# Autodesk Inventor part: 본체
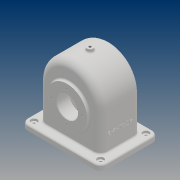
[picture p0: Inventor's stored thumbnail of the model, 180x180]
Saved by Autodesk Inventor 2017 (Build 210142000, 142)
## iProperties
Part Number: 본체
Material: 일반
Document SubType Name: Modeling
Designer: 20
Density: 1 g/cm^3
Appearance: 기본값
Author: 20
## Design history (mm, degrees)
sketch "스케치2"
  geometry: L1 (58, 0)-(58, -78); L2 (-58, 0)-(-58, -78); L3 (58, -78)-(-58, -78); A1 r 58 centre (0, 0) between (58, 0) and (-58, 0); 1 further point
  constraints: 6 end point, 2 point on circle, 2 tangent, 2 vertical, 1 centre point, 1 coincident, 1 horizontal
  dimensions: "d1" = 116 diameter of A1; "d2" = 78 distance of L2.start L2.end
extrude "돌출1" new body sketch "스케치2" stored distance "d3" = 77; taper "d4" = 0 deg
sketch "스케치9"
  geometry: L1 (-58, -78)-(58, -78) reference; C1 r 38 at (0, -13); 1 further point
  constraints: 1 centre point, 1 vertical alignment
  dimensions: "d30" = 76 diameter of C1; "d31" = 65 distance from line of L1 C1.centre
extrude "돌출4" join sketch "스케치9" distance "d32" = 5; taper "d33" = 0 deg
sketch "스케치11"
  geometry: L1 (58, 78)-(-58, 78) reference; C1 r 38 at (0, 13); 1 further point
  constraints: 1 centre point, 1 vertical alignment
  dimensions: "d37" = 76 diameter of C1; "d38" = 65 distance from line of L1 C1.centre
extrude "돌출6" join sketch "스케치11" distance "d39" = 10; taper "d40" = 0 deg
sketch "스케치12"
  geometry: C1 r 38 at (0, 0) reference; C2 r 20 at (0, 0); 1 further point
  constraints: 1 centre point, 1 coincident
  dimensions: "d41" = 40 diameter of C2
extrude "돌출7" cut sketch "스케치12" distance "d42" = 15; taper "d43" = 0 deg
sketch "스케치16"
  geometry: L1 (-58, -78)-(58, -78) reference; L2 (52, 0)-(52, -78); L3 (-52, 0)-(-52, -78); A1 r 52 centre (0, 0) between (52, 0) and (-52, 0); A2 r 58 centre (0, 0) between (58, 0) and (-58, 0) reference; 2 further points
  constraints: 4 end point, 3 point on circle, 2 point on line, 2 tangent, 2 vertical, 2 vertical alignment, 1 centre point
  dimensions: "d62" = 104 diameter of A1; "d63" = 78 distance from line of L1 A1.centre; "d64" = 78 distance of L3.start L3.end (derived)
extrude "돌출8" cut sketch "스케치16" stored distance "d65" = 67; taper "d66" = 0 deg
sketch "스케치18"
  geometry: L1 (-33.5, 26.747)-(-19.5, 15); L2 (-19.5, 15)-(-19.5, -13); L3 (-64.042, -13)-(64.042, -13); L4 (33.5, -78)-(-33.5, -78) reference; L5 (-33.5, 26.747)-(-33.5, -13); L6 (-38.5, 58)-(-38.5, 0) reference; L7 (-43.5, 25)-(-43.5, -51) reference; L8 (-33.5, -13)-(-19.5, -13); 2 further points
  constraints: 10 end point, 2 horizontal, 2 vertical, 1 midpoint, 1 point on line, 1 vertical alignment
  dimensions: "d67" = 65 distance between parallel lines of L4 L3; "d68" = 5 distance between parallel lines of L6 L5; "d69" = 24 distance between parallel lines of L7 L2; "d70" = 50 deg angle of L1 L2; "d71" = 56 diameter of L1.end L3
revolve "회전3" sketch "스케치18" stored, may be unused: angle "d72" = 90 deg
sketch "스케치19"
  geometry: L1 (-58, -65)-(58, -65) reference; C1 r 20 at (0, 0); 1 further point
  constraints: 1 centre point, 1 vertical alignment
  dimensions: "d73" = 40 diameter of C1; "d74" = 65 distance from line of L1 C1.centre
extrude "돌출9" cut sketch "스케치19" distance "d75" = 24; taper "d76" = 0 deg
sketch "스케치20"
  geometry: L1 (133, -93.5)-(-17, -93.5); L2 (-17, -93.5)-(-17, 16.5); L3 (-17, 16.5)-(133, 16.5); L4 (133, 16.5)-(133, -93.5); L5 (133, -93.5)-(-17, 16.5); L6 (-17, -93.5)-(133, 16.5); L7 (6, -5)-(6, -72) reference; L8 (6, -72)-(110, -72) reference; L9 (110, -72)-(110, -5) reference; L10 (110, -5)-(6, -5) reference; 1 further point
  constraints: 12 end point, 2 midpoint, 2 parallel, 1 horizontal, 1 perpendicular
  dimensions: "d77" = 110 distance of L1.end L2.end; "d78" = 150 distance of L2.end L3.end
extrude "돌출10" join sketch "스케치20" distance "d79" = 10; taper "d80" = 0 deg
fillet "모깎기1" dims "d81" = 12
hole "구멍1" diameter "d84" = 5; stored, may be unused: countersink angle "d88" = 90 deg, drill point angle "d90" = 118 deg; dims "d82" = 10, "d83" = 10, "d85" = 6, "d86" = 12, "d87" = 4, "d89" = 8
hole "구멍2" diameter "d93" = 5; stored, may be unused: countersink angle "d97" = 90 deg, drill point angle "d99" = 118 deg; dims "d91" = 10, "d92" = 10, "d94" = 6, "d95" = 12, "d96" = 4, "d98" = 8
hole "구멍3" diameter "d102" = 5; stored, may be unused: countersink angle "d106" = 90 deg, drill point angle "d108" = 118 deg; dims "d100" = 10, "d101" = 10, "d103" = 6, "d104" = 12, "d105" = 4, "d107" = 8
hole "구멍4" diameter "d111" = 5; stored, may be unused: countersink angle "d115" = 90 deg, drill point angle "d117" = 118 deg; dims "d109" = 10, "d110" = 10, "d112" = 6, "d113" = 12, "d114" = 4, "d116" = 8
node "작업 평면1"
sketch "스케치21"
  geometry: C1 r 6 at (0, 0); 1 further point
  constraints: 1 centre point, 1 coincident
  dimensions: "d119" = 12 diameter of C1
extrude "돌출11" join sketch "스케치21" stored distance "d120" = 10; taper "d121" = 0 deg
hole "구멍5" diameter "d124" = 4.459; stored, may be unused: countersink angle "d128" = 90 deg, drill point angle "d130" = 118 deg; dims "d122" = 10, "d123" = 10, "d125" = 10, "d126" = 12, "d127" = 4, "d129" = 12.8
sketch "스케치22"
  geometry: C1 r 20 at (0, 0) reference; 2 further points
  constraints: 1 vertical alignment
  dimensions: "d131" = 29 distance of C1.centre point (0, -29)
hole "구멍6" sketch "스케치22" at (0, -29) diameter "d132" = 3.242; stored, may be unused: countersink angle "d136" = 90 deg, drill point angle "d138" = 118 deg; dims "d133" = 8, "d134" = 12, "d135" = 4, "d137" = 10
sketch "스케치23"
  geometry: C1 r 20 at (0, 0) reference; 2 further points
  constraints: 1 vertical alignment
  dimensions: "d142" = 29 distance of C1.centre point (0, 29)
hole "구멍7" sketch "스케치23" at (0, 29) diameter "d143" = 3.242; stored, may be unused: countersink angle "d147" = 90 deg, drill point angle "d149" = 118 deg; dims "d144" = 8, "d145" = 12, "d146" = 4, "d148" = 10
fillet "모깎기2" dims "d153" = 8
chamfer "모따기1" distance "d154" = 1; stored, may be unused: second distance "d155" = 2, angle "d156" = 45 deg
fillet "모깎기3" dims "d157" = 13
fillet "모깎기4" dims "d158" = 3
fillet "모깎기5" dims "d159" = 3
fillet "모깎기6" dims "d160" = 3
fillet "모깎기7" dims "d161" = 3
sketch "스케치24"
  geometry: L1 (65, 64)-(0, 64) reference; L2 (78, -17.5)-(78, 68.5) reference; 2 further points
  constraints: 1 other
  dimensions: "d162" = 38.5 distance from line of L1 point (38, 25.5); "d163" = 40 distance from line of L2 point (38, 25.5)
feature "엠보싱1" sketch "스케치24" dims "d1" = 116, "d2" = 78, "d164" = 0.5, "d165" = 0
node "솔리드1"
pattern_circular "원형 패턴1" dims angle "d140" = 360 deg
pattern_circular "원형 패턴2" dims angle "d151" = 360 deg
node "투영된 루프3"
other parameters: "d118" = 64
